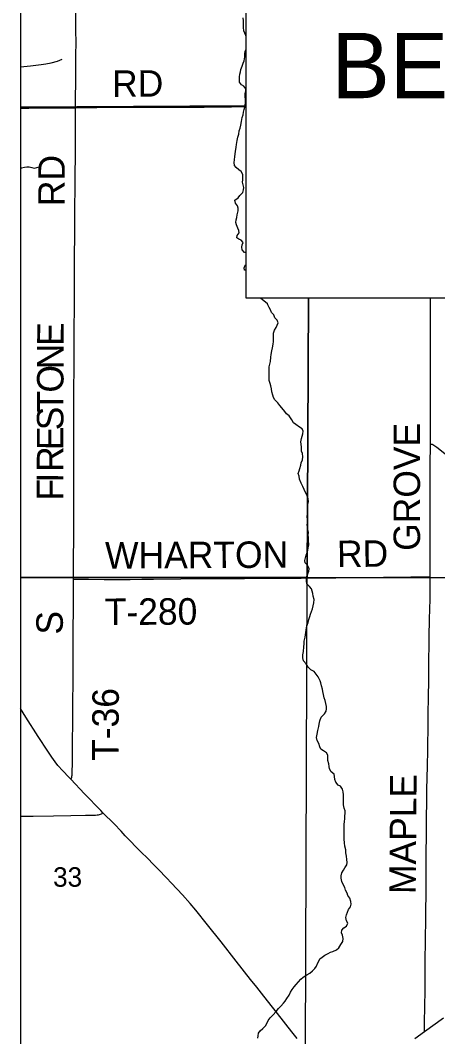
# Model space of a CAD drawing. Extents: x 0 to 34, y 0 to 22.
# Drawn here: x 2.1 to 2.995, y 15.287 to 17.466 of the extents above; entities that cross this region are included whole.
import ezdxf

# ---------------------------------------------------------------- set-up
doc = ezdxf.new("R2010")
doc.units = 0
for name, color, linetype in [('GM_X_County_Road', 7, 'Continuous'), ('GM_X_County_Road_Text', 7, 'Continuous'), ('GM_X_Minor_River', 7, 'Continuous'), ('GM_X_Section', 7, 'Continuous'), ('GM_X_Section_Text', 7, 'Continuous'), ('GM_X_State_Route', 7, 'Continuous'), ('GM_X_Township_Road', 7, 'Continuous'), ('GM_X_Township_Road_Text', 7, 'Continuous'), ('GM_X_Unincorporated', 7, 'Continuous'), ('SH_Data', 7, 'Continuous'), ('SH_Text', 7, 'Continuous')]:
    doc.layers.add(name, color=color, linetype=linetype)

msp = doc.modelspace()

# ---------------------------------------------------------------- linework, layer by layer
at = {"layer": 'GM_X_County_Road'}
for points in [[(2.9793, 16.5576), (2.9793, 16.5655), (2.9797, 16.5965), (2.9794, 16.6121), (2.9794, 16.6451), (2.9794, 16.6893), (2.9796, 16.7542), (2.9797, 16.7794), (2.9796, 16.8417), (2.9797, 16.8709)], [(2.9789, 16.2728), (2.9789, 16.2786), (2.9789, 16.317), (2.979, 16.3419), (2.9789, 16.376), (2.9789, 16.4069), (2.9787, 16.4568), (2.9789, 16.5125), (2.9793, 16.5576)], [(2.9666, 15.2977), (2.9665, 15.3109), (2.9667, 15.3202), (2.967, 15.3482), (2.9677, 15.3884), (2.9678, 15.407), (2.9682, 15.4598), (2.9684, 15.4815), (2.9687, 15.5032), (2.969, 15.5313), (2.9696, 15.5624), (2.9698, 15.5872), (2.9699, 15.6123), (2.9702, 15.6247), (2.9703, 15.6493), (2.9704, 15.6866), (2.9708, 15.7115), (2.9711, 15.7548), (2.9716, 15.7922), (2.9717, 15.8168), (2.9722, 15.8418), (2.9729, 15.8667), (2.9733, 15.9008), (2.9744, 15.9598), (2.9746, 15.9815), (2.9751, 16.0124), (2.9759, 16.0531), (2.976, 16.0748), (2.9761, 16.0997), (2.9764, 16.1214), (2.9766, 16.1429), (2.9774, 16.1832), (2.978, 16.2019), (2.9787, 16.2267), (2.9788, 16.2441), (2.979, 16.2659), (2.9789, 16.2728)], [(2.2082, 15.8386), (2.2037, 15.8434), (2.191, 15.8569), (2.1806, 15.8685), (2.1749, 15.876), (2.1674, 15.886), (2.1586, 15.8988), (2.1384, 15.9302), (2.1116, 15.9721), (2.1, 15.9908)], [(2.2771, 15.7667), (2.2725, 15.7715), (2.2378, 15.8072), (2.2082, 15.8386)], [(2.6934, 15.2826), (2.682, 15.2973), (2.6512, 15.3363), (2.6301, 15.3632), (2.6167, 15.3803), (2.6072, 15.3926), (2.5937, 15.4096), (2.5629, 15.4486), (2.5305, 15.4903), (2.5014, 15.5267), (2.4761, 15.5583), (2.4643, 15.5726), (2.4477, 15.5911), (2.4241, 15.6158), (2.4133, 15.627), (2.3961, 15.6449), (2.3853, 15.656), (2.3723, 15.6693), (2.3592, 15.6826), (2.3251, 15.7177), (2.316, 15.7272), (2.3009, 15.7428), (2.2771, 15.7667)]]:
    msp.add_lwpolyline(points, dxfattribs=at)
at = {"layer": 'GM_X_Minor_River'}
msp.add_line((2.6296, 16.8584), (2.6146, 16.8709), dxfattribs=at)
for points in [[(2.5841, 17.4309), (2.5835, 17.4339), (2.5812, 17.4388), (2.5793, 17.4441), (2.5785, 17.451), (2.5785, 17.457), (2.5781, 17.4654), (2.5777, 17.4719)], [(2.5778, 17.3749), (2.5797, 17.3799), (2.5811, 17.3879), (2.5815, 17.3936), (2.5822, 17.4), (2.5841, 17.4046)], [(2.1, 17.3665), (2.122, 17.3688), (2.133, 17.3704), (2.1444, 17.372), (2.1546, 17.3732), (2.1659, 17.3751), (2.1799, 17.379), (2.1897, 17.3832)], [(2.5841, 16.9687), (2.5803, 16.9685), (2.5757, 16.9745), (2.5749, 16.9799), (2.5757, 16.9852), (2.5779, 16.9901), (2.5737, 16.9951), (2.5688, 16.9973), (2.5638, 17), (2.5649, 17.0053), (2.5695, 17.0106), (2.5687, 17.016), (2.566, 17.0209), (2.5637, 17.0277), (2.5621, 17.033), (2.5625, 17.0387), (2.564, 17.0437), (2.5651, 17.049), (2.5673, 17.0578), (2.5669, 17.0635), (2.5654, 17.0688), (2.5612, 17.0741), (2.56, 17.0809), (2.5668, 17.0859), (2.5709, 17.0909), (2.577, 17.097), (2.5788, 17.1027), (2.5792, 17.1076), (2.578, 17.1137), (2.5761, 17.1194), (2.5768, 17.1247), (2.5772, 17.1308), (2.5771, 17.1361), (2.5737, 17.1422), (2.5687, 17.146), (2.5627, 17.1505), (2.5592, 17.1554), (2.5584, 17.1615), (2.5591, 17.1672), (2.5602, 17.1745), (2.5613, 17.1851), (2.5628, 17.1942), (2.5635, 17.2003), (2.565, 17.2091), (2.5661, 17.2159), (2.5683, 17.2224), (2.5694, 17.2293), (2.5713, 17.2353), (2.5728, 17.2418), (2.5739, 17.2498), (2.5757, 17.2582), (2.5776, 17.2639), (2.5783, 17.2692), (2.5798, 17.2749), (2.5813, 17.2799), (2.5821, 17.2848), (2.5828, 17.2901), (2.5828, 17.2959), (2.582, 17.3038), (2.5823, 17.3095), (2.5834, 17.3145), (2.5834, 17.3198), (2.5792, 17.3251), (2.5742, 17.3285), (2.57, 17.3342), (2.5696, 17.3407), (2.57, 17.3456), (2.5707, 17.3509), (2.5718, 17.3563), (2.5729, 17.3612), (2.5759, 17.3684), (2.5778, 17.3749)], [(2.1, 17.1484), (2.1023, 17.1504), (2.1087, 17.1519), (2.114, 17.1523), (2.119, 17.152), (2.125, 17.1505), (2.13, 17.1493), (2.1357, 17.1509), (2.1406, 17.1524)], [(2.5841, 16.9305), (2.5809, 16.9305), (2.5801, 16.9354), (2.5823, 16.9415), (2.5841, 16.9431)], [(2.6762, 16.618), (2.6705, 16.6222), (2.667, 16.6275), (2.6605, 16.6355), (2.6567, 16.6404), (2.6517, 16.6458), (2.6456, 16.6522), (2.6425, 16.6572), (2.641, 16.6625), (2.6394, 16.6697), (2.6383, 16.6758), (2.6367, 16.6827), (2.6356, 16.6876), (2.6337, 16.6937), (2.6336, 16.699), (2.6332, 16.7093), (2.6332, 16.7234), (2.6351, 16.7291), (2.6362, 16.7348), (2.6374, 16.7439), (2.6381, 16.7496), (2.6392, 16.7576), (2.6404, 16.7644), (2.6419, 16.7716), (2.6426, 16.7777), (2.643, 16.7838), (2.6426, 16.7895), (2.643, 16.7956), (2.6449, 16.8017), (2.6483, 16.8078), (2.6509, 16.8127), (2.6528, 16.818), (2.6509, 16.8234), (2.6459, 16.8283), (2.6432, 16.8348), (2.6387, 16.8401), (2.636, 16.8454), (2.6337, 16.8507), (2.6306, 16.8565), (2.6296, 16.8584)], [(2.7567, 15.9901), (2.7563, 15.9951), (2.7551, 16.0015), (2.7532, 16.0076), (2.7517, 16.0133), (2.7498, 16.0206), (2.7486, 16.027), (2.7478, 16.0323), (2.7459, 16.0392), (2.744, 16.0453), (2.7428, 16.0502), (2.7382, 16.0586), (2.734, 16.0643), (2.7298, 16.0696), (2.7229, 16.0734), (2.7172, 16.0791), (2.7126, 16.086), (2.7072, 16.0928), (2.7057, 16.0989), (2.706, 16.1058), (2.7068, 16.1126), (2.7075, 16.1225), (2.7083, 16.129), (2.7087, 16.1347), (2.7109, 16.1434), (2.7117, 16.1487), (2.7128, 16.1586), (2.7135, 16.1643), (2.7151, 16.1696), (2.717, 16.1753), (2.7185, 16.1814), (2.7207, 16.1879), (2.7223, 16.1928), (2.7245, 16.1989), (2.7264, 16.2046), (2.7279, 16.2107), (2.7294, 16.2175), (2.7302, 16.224), (2.7279, 16.2316), (2.7271, 16.2369), (2.726, 16.2423), (2.724, 16.2472), (2.7198, 16.2522), (2.7145, 16.2582), (2.7133, 16.2643), (2.7144, 16.2738), (2.7182, 16.2852), (2.719, 16.2902), (2.7155, 16.2978), (2.7109, 16.3027), (2.7101, 16.3077), (2.7113, 16.3134), (2.7128, 16.3191), (2.7151, 16.3248), (2.7166, 16.3301), (2.7173, 16.3351), (2.7185, 16.3415), (2.7181, 16.3506), (2.7177, 16.3564), (2.7173, 16.3628), (2.7176, 16.3681), (2.7165, 16.3742), (2.7157, 16.3795), (2.7153, 16.3849), (2.7161, 16.3898), (2.7157, 16.3959), (2.7149, 16.4024), (2.7156, 16.4073), (2.716, 16.4149), (2.7156, 16.4233), (2.7163, 16.4294), (2.7175, 16.4347), (2.7171, 16.44), (2.714, 16.4491), (2.7106, 16.4552), (2.7083, 16.4602), (2.706, 16.4666), (2.7021, 16.4739), (2.6983, 16.4826), (2.6979, 16.4891), (2.696, 16.4944), (2.6979, 16.5005), (2.699, 16.5054), (2.7013, 16.5127), (2.7024, 16.5176), (2.7047, 16.5241), (2.7054, 16.5301), (2.7046, 16.5377), (2.7031, 16.5427), (2.7027, 16.5507), (2.7019, 16.5571), (2.7015, 16.5628), (2.703, 16.5693), (2.7053, 16.5796), (2.7061, 16.5853), (2.7041, 16.5902), (2.6984, 16.594), (2.6904, 16.5997), (2.6854, 16.6035), (2.6823, 16.6096), (2.6762, 16.618)], [(2.6826, 15.3875), (2.6868, 15.3935), (2.6917, 15.3989), (2.6963, 15.4042), (2.7012, 15.4099), (2.7065, 15.4144), (2.7145, 15.419), (2.721, 15.4232), (2.7267, 15.4277), (2.7317, 15.4331), (2.7347, 15.438), (2.7374, 15.4433), (2.7397, 15.4483), (2.7423, 15.4536), (2.7473, 15.4574), (2.753, 15.4612), (2.7599, 15.465), (2.7648, 15.4676), (2.7702, 15.4692), (2.7778, 15.4726), (2.7831, 15.4775), (2.7873, 15.4844), (2.7911, 15.4908), (2.7918, 15.4973), (2.7907, 15.5041), (2.7888, 15.5095), (2.7891, 15.5148), (2.7937, 15.5201), (2.799, 15.5239), (2.8024, 15.53), (2.7994, 15.5349), (2.7982, 15.5425), (2.7994, 15.5479), (2.8039, 15.5596), (2.8081, 15.5653), (2.8092, 15.5707), (2.8088, 15.5768), (2.8061, 15.584), (2.8023, 15.5893), (2.8004, 15.5946), (2.7973, 15.6011), (2.7954, 15.6068), (2.7923, 15.6133), (2.7893, 15.6197), (2.7877, 15.6266), (2.7877, 15.6315), (2.7896, 15.638), (2.7926, 15.6437), (2.7957, 15.649), (2.7999, 15.6551), (2.8006, 15.6604), (2.8002, 15.6665), (2.7991, 15.6737), (2.7979, 15.6813), (2.7975, 15.6874), (2.7959, 15.6954), (2.7948, 15.7026), (2.7944, 15.7102), (2.7943, 15.7418), (2.7947, 15.7483), (2.7954, 15.754), (2.7958, 15.7597), (2.7962, 15.7661), (2.7962, 15.7711), (2.7942, 15.7764), (2.7927, 15.784), (2.7927, 15.789), (2.793, 15.7947), (2.793, 15.7996), (2.793, 15.8057), (2.7922, 15.8118), (2.7907, 15.8175), (2.7865, 15.8236), (2.7815, 15.8262), (2.7765, 15.8323), (2.7746, 15.8384), (2.7738, 15.8445), (2.7731, 15.8498), (2.7662, 15.8544), (2.7627, 15.8612), (2.762, 15.8662), (2.7612, 15.8719), (2.7593, 15.8791), (2.7592, 15.8848), (2.7592, 15.8901), (2.7562, 15.8954), (2.7497, 15.9), (2.7443, 15.9031), (2.7424, 15.908), (2.7397, 15.9152), (2.7363, 15.9221), (2.7351, 15.9282), (2.7362, 15.9354), (2.7381, 15.9434), (2.7396, 15.9517), (2.7408, 15.9571), (2.7419, 15.9639), (2.7449, 15.9719), (2.7521, 15.9791), (2.7556, 15.9848), (2.7567, 15.9901)], [(2.6095, 15.2833), (2.6099, 15.2883), (2.6107, 15.294), (2.6141, 15.2993), (2.6202, 15.3042), (2.6266, 15.3103), (2.6312, 15.321), (2.6358, 15.3274), (2.6415, 15.3331), (2.6483, 15.3403), (2.6537, 15.3468), (2.6586, 15.3521), (2.6639, 15.3582), (2.6677, 15.3631), (2.6715, 15.3685), (2.6761, 15.3757), (2.6795, 15.3818), (2.6826, 15.3875)]]:
    msp.add_lwpolyline(points, dxfattribs=at)
at = {"layer": 'GM_X_Section'}
for points in [[(2.7176, 16.8709), (2.7146, 16.2714), (3.7413, 16.2718), (3.7435, 16.8709)], [(2.7146, 16.2714), (3.7413, 16.2718), (3.7269, 15.2595), (2.7116, 15.2583)]]:
    msp.add_lwpolyline(points, close=True, dxfattribs=at)
at = {"layer": 'GM_X_State_Route'}
msp.add_lwpolyline([(2.946, 15.2827), (2.9666, 15.2977), (3.0069, 15.3269)], dxfattribs=at)
at = {"layer": 'GM_X_Township_Road'}
for points in [[(2.1, 20.9), (2.1, 15.2557), (2.7077, 15.2596), (2.915, 15.2604), (3.727, 15.2572), (4.7402, 15.2622)], [(2.2186, 17.279), (2.2185, 17.2969), (2.2185, 17.3093), (2.2187, 17.3248), (2.2189, 17.3465), (2.219, 17.3683), (2.2193, 17.3962), (2.2194, 17.4149), (2.2193, 17.449), (2.2192, 17.4614), (2.2193, 17.4956)], [(2.1, 17.2782), (2.1181, 17.2782), (2.1927, 17.2788), (2.2175, 17.279), (2.2186, 17.279)], [(2.2139, 16.2678), (2.2138, 16.2844), (2.2141, 16.3092), (2.2145, 16.3588), (2.2148, 16.3869), (2.2147, 16.4224), (2.2147, 16.4397), (2.2147, 16.4549), (2.2148, 16.4769), (2.2146, 16.5018), (2.2147, 16.5359), (2.2149, 16.5484), (2.215, 16.6012), (2.215, 16.6322), (2.215, 16.6788), (2.2153, 16.7161), (2.2152, 16.7347), (2.2155, 16.7627), (2.2154, 16.7751), (2.2155, 16.7906), (2.2154, 16.8), (2.2159, 16.8559), (2.2162, 16.9179), (2.2163, 16.9583), (2.2166, 17.008), (2.2167, 17.0608), (2.2174, 17.1105), (2.2176, 17.1416), (2.218, 17.1695), (2.2181, 17.2099), (2.2183, 17.2348), (2.2186, 17.2627), (2.2186, 17.279)], [(2.2186, 17.279), (2.2393, 17.2792), (2.2641, 17.2795), (2.3168, 17.2799), (2.3417, 17.2801), (2.3665, 17.2803), (2.4131, 17.2804), (2.4504, 17.2805), (2.4722, 17.2805), (2.4939, 17.2806), (2.5342, 17.2811), (2.5529, 17.2813), (2.5839, 17.2814), (2.5841, 17.2814)], [(2.9793, 16.5576), (2.9815, 16.5576), (2.9826, 16.5575), (2.9842, 16.5569), (2.9867, 16.5554), (2.9929, 16.5508), (3.0173, 16.5315)], [(2.2082, 15.8386), (2.2086, 15.8394), (2.2095, 15.8411), (2.2103, 15.8431), (2.2107, 15.8452), (2.211, 15.8473), (2.2115, 15.8795), (2.2118, 15.903), (2.212, 15.926), (2.2123, 15.9532), (2.2125, 15.9679), (2.2125, 15.9928), (2.2131, 16.0582), (2.2131, 16.0762), (2.213, 16.1014), (2.2132, 16.122), (2.2133, 16.1387), (2.2134, 16.1548), (2.2136, 16.1693), (2.2138, 16.1943), (2.2139, 16.21), (2.214, 16.2252), (2.2141, 16.2502), (2.2139, 16.2627), (2.2139, 16.2678)], [(2.2139, 16.2678), (2.2162, 16.2677), (2.2459, 16.2676), (2.28, 16.2672), (2.3358, 16.2673), (2.3606, 16.2677), (2.3855, 16.268), (2.4442, 16.2688), (2.494, 16.2691), (2.5499, 16.2694), (2.5807, 16.2695), (2.6336, 16.2698), (2.6522, 16.2698), (2.6832, 16.2699), (2.7018, 16.2702), (2.7235, 16.2706), (2.7481, 16.2708), (2.7762, 16.271), (2.8445, 16.2717), (2.8786, 16.2721), (2.9127, 16.2722), (2.9375, 16.2726), (2.953, 16.2728), (2.9715, 16.2728), (2.9743, 16.2728), (2.9789, 16.2728)], [(2.1, 15.7596), (2.1278, 15.7599), (2.1713, 15.7604), (2.2084, 15.7611), (2.2396, 15.7616), (2.2551, 15.7616), (2.2612, 15.762), (2.2645, 15.7623), (2.2673, 15.7628), (2.2698, 15.7633), (2.2718, 15.7638), (2.2737, 15.7646), (2.2754, 15.7655), (2.2771, 15.7667)]]:
    msp.add_lwpolyline(points, dxfattribs=at)
at = {"layer": 'GM_X_Unincorporated'}
for points in [[(2.7229, 17.5881), (2.7303, 18.305), (2.1, 18.2939), (2.1, 17.28), (2.5841, 17.2828), (2.5841, 17.5881)], [(2.5841, 17.2828), (2.1, 17.28), (2.1, 16.2714), (2.7146, 16.2714), (2.7176, 16.8709), (2.5841, 16.8709)], [(2.1, 16.2714), (2.1, 15.2567), (2.7116, 15.2583), (2.7146, 16.2714)]]:
    msp.add_lwpolyline(points, close=True, dxfattribs=at)
at = {"layer": 'SH_Data'}
msp.add_line((2.1, 20.9), (2.1, 14.1), dxfattribs=at)
at = {"layer": 'SH_Text'}
msp.add_lwpolyline([(2.5841, 17.5881), (4.804, 17.5881), (4.804, 16.8709), (2.5841, 16.8709)], close=True, dxfattribs=at)

# ---------------------------------------------------------------- texts
at = {"layer": 'GM_X_County_Road_Text'}
for s, rotation, p in [('GROVE', 90, (2.957, 16.3287)), ('MAPLE', 89.5953, (2.9478, 15.5924))]:
    msp.add_text(s, height=0.05682, rotation=rotation, dxfattribs=at).set_placement(p)
at = {"layer": 'GM_X_Section_Text'}
msp.add_text('33', height=0.04186, rotation=0, dxfattribs=at).set_placement((2.1702, 15.6082))
at = {"layer": 'GM_X_Township_Road_Text'}
for s, height, rotation, p in [('RD', 0.05682, 0.4939, (2.297, 17.3021)), ('RD', 0.05682, 90, (2.1953, 17.0681)), ('E', 0.0568, 89.3271, (2.1927, 16.7679)), ('N', 0.0568, 89.8488, (2.1926, 16.718)), ('O', 0.0568, 89.8713, (2.1925, 16.668)), ('T', 0.0568, 89.8693, (2.1924, 16.6255)), ('S', 0.0568, 89.8719, (2.1923, 16.5872)), ('E', 0.0568, 89.8693, (2.1922, 16.5447)), ('R', 0.0568, 89.8718, (2.1921, 16.498)), ('F', 0.0568, 89.8693, (2.192, 16.4363)), ('I', 0.0568, 89.8721, (2.1921, 16.4747)), ('WHARTON', 0.05682, 0.2681, (2.2818, 16.2905)), ('RD', 0.05682, 0.4936, (2.7791, 16.2938)), ('T-280', 0.05682, 0.2811, (2.2811, 16.1695)), ('S', 0.0568, 90, (2.1911, 16.149)), ('T-36', 0.05682, 89.6458, (2.3104, 15.878))]:
    msp.add_text(s, height=height, rotation=rotation, dxfattribs=at).set_placement(p)
at = {"layer": 'SH_Text'}
msp.add_text('BEGIN ACQUISTION', height=0.14, dxfattribs=at).set_placement((2.7672, 17.2995))

doc.saveas('drawing.dxf')
